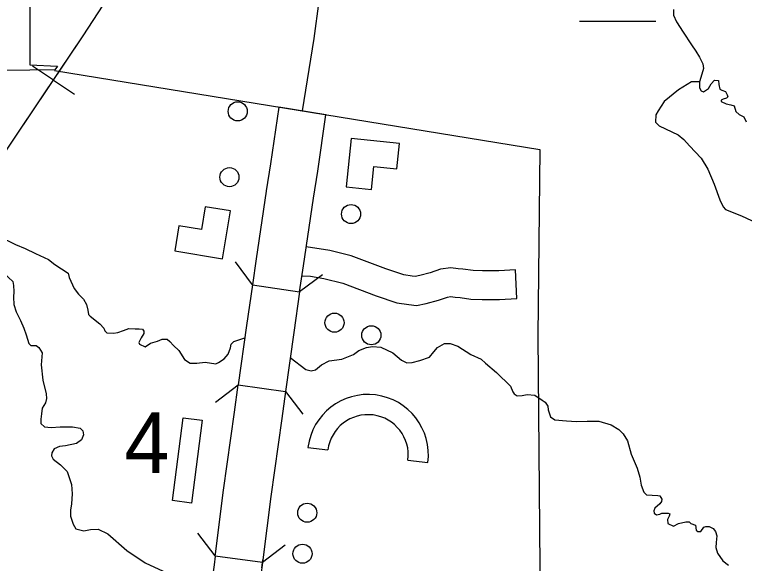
# Model space of a CAD drawing. Extents: x 22866 to 28196, y 1324810 to 1328105.
# Drawn here: x 25647.4 to 25739.1, y 1325934.5 to 1326003.5 of the extents above; entities that cross this region are included whole.
import ezdxf

# ---------------------------------------------------------------- set-up
doc = ezdxf.new("R2010")
doc.units = 0
for name, color, linetype in [('Level 15', 7, 'Continuous'), ('Level 35', 7, 'Continuous'), ('Level 37', 7, 'Continuous'), ('Level 40', 7, 'Continuous'), ('Level 44', 7, 'Continuous'), ('Level 45', 7, 'Continuous'), ('Level 46', 7, 'Continuous'), ('Level 5', 7, 'Continuous'), ('Level 56', 7, 'Continuous'), ('Level 57', 7, 'Continuous'), ('Level 58', 7, 'Continuous'), ('Level 6', 7, 'Continuous'), ('Level 63', 7, 'Continuous')]:
    doc.layers.add(name, color=color, linetype=linetype)

msp = doc.modelspace()

# ---------------------------------------------------------------- linework, layer by layer
at = {"layer": 'Level 15'}
for p, q in [((25686.536, 1325990.883), (25680.612, 1325991.848)), ((25678.575, 1325934.608), (25678.618, 1325934.926))]:
    msp.add_line(p, q, dxfattribs=at)
for points in [[(25741.705, 1326055.535), (25738.913, 1326054.35), (25731.292, 1326051.151), (25725.77, 1326048.846), (25722.463, 1326047.289), (25719.108, 1326045.244), (25716.871, 1326043.443), (25713.807, 1326041.107), (25709.285, 1326037.31), (25705.2, 1326034.097), (25699.899, 1326029.862), (25693.432, 1326024.508), (25692.08, 1326023.413), (25690.329, 1326021.66), (25689.065, 1326020.103), (25688.092, 1326018.35), (25687.266, 1326016.452), (25686.634, 1326012.752), (25685.657, 1326005.152), (25685.029, 1326000.471), (25683.551, 1325991.369)], [(25680.612, 1325991.848), (25679.582, 1325984.709), (25679.05, 1325981.32)], [(25684.978, 1325980.389), (25685.516, 1325983.815), (25686.536, 1325990.883)], [(25679.046, 1325981.295), (25677.781, 1325972.762), (25677.307, 1325969.501), (25683.242, 1325968.625)], [(25683.244, 1325968.627), (25683.718, 1325971.891), (25684.982, 1325980.414)], [(25677.307, 1325969.501), (25676.563, 1325964.376), (25675.53, 1325956.934)], [(25683.243, 1325968.626), (25682.505, 1325963.532), (25681.474, 1325956.109)], [(25678.618, 1325934.926), (25678.575, 1325934.608), (25672.628, 1325935.411), (25672.669, 1325935.708), (25673.691, 1325943.697), (25675.054, 1325953.512), (25675.53, 1325956.934)], [(25675.53, 1325956.934), (25681.474, 1325956.109), (25680.998, 1325952.686), (25679.639, 1325942.903), (25678.618, 1325934.926), (25678.575, 1325934.608)], [(25672.628, 1325935.411), (25672.481, 1325934.319), (25672.171, 1325932.02), (25672.019, 1325929.837), (25671.923, 1325928.552), (25671.609, 1325925.046), (25671.385, 1325922.705)], [(25678.483, 1325933.922), (25678.575, 1325934.608), (25678.144, 1325931.41), (25678.004, 1325929.407), (25677.905, 1325928.063), (25677.595, 1325924.609), (25677.354, 1325922.085)]]:
    msp.add_lwpolyline(points, dxfattribs=at)
at = {"layer": 'Level 35'}
for points in [[(25730.229, 1326004.112), (25730.229, 1326003.405), (25730.621, 1326002.568), (25731.457, 1326001.26)], [(25731.457, 1326001.26), (25732.495, 1325999.669), (25733.044, 1325998.884), (25733.488, 1325998.126), (25733.932, 1325997.288), (25733.985, 1325996.713), (25733.671, 1325995.588), (25733.514, 1325995.012), (25733.514, 1325994.803), (25733.488, 1325994.28), (25733.723, 1325993.887), (25734.011, 1325993.783), (25734.638, 1325994.201), (25734.978, 1325994.777), (25735.396, 1325995.222), (25735.867, 1325995.195), (25735.919, 1325994.698), (25736.05, 1325994.097), (25736.285, 1325993.966), (25736.755, 1325993.809), (25736.985, 1325993.409), (25737.037, 1325993.147), (25736.881, 1325992.964), (25736.462, 1325992.859), (25736.201, 1325992.728), (25736.227, 1325992.571), (25736.855, 1325992.257), (25737.43, 1325992.153), (25737.874, 1325992.022), (25738.057, 1325991.289), (25738.475, 1325990.923), (25739.05, 1325990.609), (25739.364, 1325989.981)], [(25733.514, 1325995.012), (25732.489, 1325995.005), (25730.843, 1325994.01), (25729.065, 1325992.545), (25728.307, 1325991.394), (25727.994, 1325990.897), (25727.967, 1325989.955), (25728.438, 1325989.51), (25730.032, 1325988.752), (25730.816, 1325988.359), (25731.548, 1325987.757), (25732.228, 1325986.999)], [(25732.228, 1325986.999), (25733.692, 1325985.445), (25734.554, 1325984.058), (25735.338, 1325982.174), (25736.07, 1325980.186), (25736.462, 1325979.296), (25736.776, 1325978.956), (25738.762, 1325978.171), (25741.298, 1325976.994), (25742.343, 1325976.183), (25743.546, 1325974.823), (25744.33, 1325973.619), (25745.088, 1325973.017), (25745.872, 1325972.887), (25747.179, 1325972.782), (25748.564, 1325972.154), (25749.505, 1325971.683), (25751.466, 1325970.977), (25753.609, 1325970.427), (25755.517, 1325970.035), (25756.006, 1325969.619), (25756.79, 1325968.965)], [(25641.486, 1325975.898), (25642.871, 1325975.322), (25643.76, 1325974.877), (25645.434, 1325975.139), (25645.721, 1325975.165), (25646.506, 1325975.06), (25647.525, 1325974.563), (25648.728, 1325974.092), (25650.061, 1325973.464), (25651.682, 1325972.705), (25652.493, 1325972.077), (25654.14, 1325970.952)], [(25639.527, 1325974.971), (25639.629, 1325974.118), (25639.891, 1325973.752), (25640.623, 1325973.726), (25641.407, 1325973.647), (25642.061, 1325973.464), (25643.211, 1325972.862), (25643.76, 1325972.339), (25645.146, 1325971.789), (25646.087, 1325971.03), (25646.636, 1325970.428), (25647.211, 1325969.931), (25647.29, 1325969.434), (25647.316, 1325968.649), (25647.29, 1325967.968), (25647.316, 1325967.026), (25647.63, 1325966.11), (25648.153, 1325965.037), (25648.597, 1325964.043), (25648.856, 1325963.221), (25649.198, 1325962.133)], [(25654.14, 1325970.952), (25654.291, 1325970.427), (25654.919, 1325969.04), (25655.441, 1325968.334), (25656.095, 1325967.706), (25656.435, 1325967.052), (25656.618, 1325966.32), (25656.722, 1325965.77), (25656.905, 1325965.587), (25658.108, 1325964.619), (25658.63, 1325964.07), (25658.761, 1325963.703), (25659.022, 1325963.468), (25659.859, 1325963.442), (25660.382, 1325963.52), (25661.087, 1325963.782), (25661.793, 1325964.017), (25662.551, 1325963.991), (25663.074, 1325963.991), (25663.492, 1325963.913), (25663.675, 1325963.677), (25663.649, 1325963.389), (25663.309, 1325962.84), (25663.048, 1325962.238), (25663.1, 1325962.029), (25663.806, 1325961.715), (25664.511, 1325962.186), (25665.374, 1325962.421), (25665.949, 1325962.657), (25666.576, 1325962.657), (25666.911, 1325962.395), (25667.381, 1325961.898), (25668.061, 1325961.27), (25668.767, 1325960.119), (25669.473, 1325959.648), (25670.309, 1325959.674), (25671.355, 1325959.779), (25672.688, 1325959.569), (25673.054, 1325959.753), (25673.759, 1325960.197), (25674.256, 1325960.773), (25674.543, 1325961.584), (25674.648, 1325962.055), (25674.988, 1325962.369), (25676.35, 1325962.841)], [(25649.198, 1325962.133), (25649.457, 1325961.861), (25650.111, 1325961.887), (25650.477, 1325961.625), (25650.869, 1325960.971), (25650.765, 1325959.453), (25650.948, 1325957.543), (25651.366, 1325955.789)], [(25692.391, 1325961.767), (25693.454, 1325961.67), (25694.944, 1325960.964), (25696.042, 1325960.022), (25696.722, 1325959.682), (25697.401, 1325959.761), (25698.342, 1325959.996), (25699.571, 1325960.415), (25700.12, 1325961.095), (25700.564, 1325961.618), (25701.427, 1325962.115), (25702.159, 1325962.141), (25703.126, 1325961.801), (25704.772, 1325960.755), (25706.053, 1325960.179), (25706.602, 1325959.656), (25707.987, 1325958.505), (25709.739, 1325956.778), (25710.047, 1325956.053), (25710.204, 1325955.818), (25710.596, 1325955.556), (25711.223, 1325955.609), (25711.851, 1325955.713), (25712.792, 1325955.635), (25713.733, 1325955.007), (25714.099, 1325954.745), (25714.438, 1325954.248), (25714.464, 1325953.777), (25714.752, 1325952.914), (25715.327, 1325952.547), (25716.791, 1325952.391), (25718.045, 1325952.338), (25719.379, 1325952.364), (25720.842, 1325952.364), (25722.384, 1325951.893), (25723.352, 1325951.318), (25723.9, 1325950.795), (25724.449, 1325949.879), (25724.894, 1325948.204), (25725.652, 1325946.452), (25726.018, 1325945.34), (25726.174, 1325944.319), (25726.514, 1325943.456), (25726.854, 1325943.09), (25728.239, 1325943.011)], [(25682.063, 1325960.351), (25684.021, 1325958.874), (25684.699, 1325958.691), (25685.255, 1325958.811), (25685.987, 1325959.465), (25686.954, 1325959.962), (25688.548, 1325960.171), (25690.012, 1325960.747), (25690.692, 1325961.27), (25691.633, 1325961.636), (25692.391, 1325961.767)], [(25651.366, 1325955.789), (25651.444, 1325955.221), (25651.287, 1325954.672), (25650.869, 1325953.991), (25650.791, 1325953.311), (25650.712, 1325952.631), (25650.712, 1325952.081), (25651.157, 1325951.636), (25652.02, 1325951.584), (25653.144, 1325951.636), (25654.712, 1325951.662), (25655.654, 1325951.505), (25655.994, 1325951.165), (25656.072, 1325950.642), (25655.837, 1325950.014), (25655.183, 1325949.543), (25653.824, 1325949.281), (25653.039, 1325949.176), (25652.386, 1325948.888), (25652.098, 1325948.391), (25652.072, 1325948.025), (25652.255, 1325947.58), (25653.196, 1325946.9)], [(25653.196, 1325946.9), (25654.007, 1325946.049), (25654.556, 1325944.427), (25654.66, 1325943.249), (25654.556, 1325941.967), (25654.451, 1325941.182), (25654.451, 1325940.423), (25654.791, 1325939.402), (25655.131, 1325938.853), (25656.124, 1325938.565), (25656.935, 1325938.748), (25657.928, 1325938.774), (25659.131, 1325938.198), (25661.536, 1325936.105), (25663.837, 1325934.561)], [(25728.239, 1325943.011), (25728.521, 1325942.99), (25728.783, 1325942.546), (25728.731, 1325942.284), (25728.495, 1325941.996), (25727.894, 1325941.421), (25727.763, 1325941.107), (25727.79, 1325940.793), (25728.103, 1325940.61), (25728.521, 1325940.662), (25728.783, 1325940.819), (25729.541, 1325940.819), (25729.75, 1325940.714), (25729.671, 1325940.426), (25729.489, 1325940.008), (25729.515, 1325939.511), (25730.22, 1325939.171), (25730.848, 1325939.485), (25731.763, 1325939.72), (25732.207, 1325939.694), (25732.39, 1325939.511), (25732.991, 1325939.275), (25733.069, 1325938.647), (25733.305, 1325938.517), (25733.671, 1325938.49), (25734.037, 1325939.04), (25734.272, 1325939.144), (25734.716, 1325939.118), (25735.213, 1325938.883), (25735.527, 1325938.49), (25735.683, 1325937.967), (25735.605, 1325937.104), (25735.553, 1325936.502), (25735.762, 1325935.796), (25736.415, 1325934.828), (25737.121, 1325934.252)], [(25663.837, 1325934.561), (25666.101, 1325933.524), (25667.879, 1325933.263), (25670.546, 1325932.896), (25672.176, 1325932.1)]]:
    msp.add_lwpolyline(points, dxfattribs=at)
at = {"layer": 'Level 37'}
for points in [[(25677.306, 1325969.506), (25675.161, 1325972.398)], [(25686.134, 1325970.77), (25683.242, 1325968.625)], [(25672.657, 1325954.77), (25675.532, 1325956.939)], [(25681.475, 1325956.106), (25683.643, 1325953.231)], [(25672.623, 1325935.425), (25670.455, 1325938.3)], [(25681.441, 1325936.762), (25678.566, 1325934.594)]]:
    msp.add_lwpolyline(points, dxfattribs=at)
at = {"layer": 'Level 40'}
for q in [(25649.669, 1325997.014), (25654.927, 1325993.476)]:
    msp.add_line((25652.298, 1325995.245), q, dxfattribs=at)
for points in [[(25653.036, 1325996.341), (25656.031, 1326000.792), (25663.489, 1326012.302), (25670.201, 1326022.413), (25674.429, 1326028.619), (25683.067, 1326041.543), (25687.146, 1326047.825), (25693.492, 1326057.226), (25703.28, 1326071.933), (25704.923, 1326074.403)], [(25634.632, 1325968.941), (25639.051, 1325975.556), (25645.237, 1325984.75), (25653.036, 1325996.341)], [(25634.632, 1325968.941), (25639.051, 1325975.556), (25645.237, 1325984.75), (25653.036, 1325996.341)]]:
    msp.add_lwpolyline(points, dxfattribs=at)
at = {"layer": 'Level 44'}
msp.add_line((25718.423, 1326002.659), (25728.024, 1326002.659), dxfattribs=at)
at = {"layer": 'Level 45'}
msp.add_lwpolyline([(25624.597, 1325954.008), (25629.959, 1325961.868), (25635.142, 1325969.704), (25639.051, 1325975.556), (25645.237, 1325984.75), (25656.031, 1326000.792), (25663.489, 1326012.302), (25670.201, 1326022.413), (25674.429, 1326028.619)], dxfattribs=at)
at = {"layer": 'Level 46'}
for points in [[(25710.551, 1325967.784), (25710.367, 1325971.38), (25708.26, 1325971.273), (25707.757, 1325971.273), (25706.244, 1325971.273), (25705.05, 1325971.306), (25703.76, 1325971.485), (25703.147, 1325971.521), (25702.245, 1325971.657), (25700.956, 1325971.488), (25699.644, 1325971.011), (25698.348, 1325970.678), (25697.754, 1325970.559), (25697.401, 1325970.599), (25696.321, 1325970.753), (25694.083, 1325971.534), (25689.731, 1325973.135), (25687.033, 1325973.839), (25684.076, 1325974.303)], [(25683.536, 1325970.632), (25684.609, 1325970.575), (25686.297, 1325970.31), (25688.652, 1325969.695), (25692.869, 1325968.144), (25695.465, 1325967.238), (25696.947, 1325967.026), (25697.913, 1325966.919), (25699.15, 1325967.167), (25700.71, 1325967.567), (25701.815, 1325967.969), (25702.21, 1325968.021), (25702.773, 1325967.936), (25703.405, 1325967.899), (25704.751, 1325967.712), (25706.194, 1325967.672), (25707.757, 1325967.672), (25708.352, 1325967.672), (25710.551, 1325967.784)]]:
    msp.add_lwpolyline(points, dxfattribs=at)
at = {"layer": 'Level 5'}
msp.add_lwpolyline([(25713.437, 1325986.5), (25713.188, 1325963.083), (25713.728, 1325900.218)], dxfattribs=at)
at = {"layer": 'Level 56'}
msp.add_lwpolyline([(25668.619, 1325952.798), (25670.999, 1325952.486), (25669.633, 1325942.073), (25667.253, 1325942.386)], close=True, dxfattribs=at)
for centre in [(25675.458, 1325991.315), (25674.416, 1325983.038), (25689.703, 1325978.407), (25687.618, 1325964.749), (25692.253, 1325963.168), (25684.195, 1325940.856), (25683.604, 1325935.708)]:
    msp.add_circle(centre, 1.2, dxfattribs=at)
at = {"layer": 'Level 57'}
for p, q in [((25684.282, 1325949.075), (25686.797, 1325948.756)), ((25696.855, 1325947.477), (25699.37, 1325947.157))]:
    msp.add_line(p, q, dxfattribs=at)
for radius in [7.605, 5.07]:
    msp.add_arc((25691.826, 1325948.116), radius, 352.7543, 172.7543, dxfattribs=at)
at = {"layer": 'Level 58'}
for points in [[(25689.719, 1325987.91), (25689.081, 1325981.846), (25692.281, 1325981.509), (25692.582, 1325984.379), (25695.447, 1325984.077), (25695.783, 1325987.272)], [(25673.565, 1325972.794), (25674.537, 1325978.814), (25671.361, 1325979.327), (25670.901, 1325976.478), (25668.057, 1325976.937), (25667.545, 1325973.766)]]:
    msp.add_lwpolyline(points, close=True, dxfattribs=at)
at = {"layer": 'Level 6'}
msp.add_lwpolyline([(25692.231, 1326056.724), (25687.382, 1326049.534), (25670.535, 1326050.712), (25671.146, 1326046.365), (25684.478, 1326045.433), (25673.339, 1326028.919), (25649.322, 1326029.36), (25649.356, 1326012.12), (25649.325, 1325997.178), (25652.79, 1325996.996), (25652.474, 1325996.526), (25649.325, 1325996.51), (25617.16, 1325996.348)], dxfattribs=at)
at = {"layer": 'Level 63'}
msp.add_line((25652.417, 1325996.442), (25713.437, 1325986.5), dxfattribs=at)

# ---------------------------------------------------------------- texts
at = {"layer": 'Level 56'}
msp.add_text('4', height=7.605, dxfattribs=at).set_placement((25661.213, 1325945.864))

doc.saveas('drawing.dxf')
